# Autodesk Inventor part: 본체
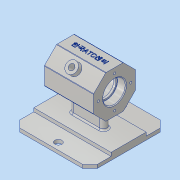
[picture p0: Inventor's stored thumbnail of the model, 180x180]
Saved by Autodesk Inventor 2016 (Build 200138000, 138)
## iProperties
Created: 2018-06
Part Number: 본체
Material: 알루미늄 6061
Document SubType Name: Modeling
Designer: 605-17
Density: 2.7 g/cm^3
Appearance: 알루미늄 - 평지
Mass: 552.439 g
Surface Area: 602.386 cm^2
Volume: 204.607 cm^3
Author: 605-17
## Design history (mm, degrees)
sketch "스케치1"
  geometry: L1 (-45, 55)-(45, 55); L2 (55, 45)-(55, -45); L3 (45, -55)-(-45, -55); L4 (-55, -45)-(-55, 45); L5 (-45, 55)-(-55, 45); L6 (45, 55)-(55, 45); L7 (-45, -55)-(-55, -45); L8 (45, -55)-(55, -45); 7 further points
  constraints: 16 end point, 8 point on line, 2 midpoint, 2 parallel, 2 perpendicular, 1 horizontal, 1 horizontal alignment, 1 vertical alignment
  dimensions: "d0" = 110 distance of point (-55, 55) point (55, 55); "d1" = 10 distance of L1.start point (-55, 55); "d2" = 10 distance of L4.end point (-55, 55) (= d1); "d3" = 10 distance of L1.end point (55, 55) (= d1); "d4" = 10 distance of L2.start point (55, 55) (= d3); "d5" = 10 distance of L3.end point (-55, -55) (= d1); "d6" = 10 distance of L4.start point (-55, -55) (= d5); "d7" = 10 distance of L3.start point (55, -55) (= d1); "d8" = 10 distance of L2.end point (55, -55) (= d7)
extrude "돌출1" new body sketch "스케치1" distance "d9" = 5; taper "d10" = 0 deg
sketch "스케치2"
  geometry: L1 (-55, 45)-(-55, -45) reference; L2 (-45, -55)-(45, -55) reference; L3 (55, -45)-(55, 45) reference; L4 (45, 55)-(-45, 55) reference; L5 (-55, 45)-(-55, -45) reference; L6 (55, -45)-(55, 45) reference; L7 (-55, 25)-(55, 25); L8 (-55, -25)-(55, -25); L9 (55, -25)-(55, 25); L10 (-55, 25)-(-55, -25); 1 further point
  constraints: 8 end point, 4 point on line, 2 collinear, 2 perpendicular
  dimensions: "d11" = 30 distance between parallel lines of L7 L4; "d12" = 30 distance between parallel lines of L2 L8
extrude "돌출2" join sketch "스케치2" distance "d13" = 5; taper "d14" = 0 deg
sketch "스케치3" dims "d15" = 60
  geometry: L1 (25, 10)-(-25, 10) reference; L2 (-30, 74.426)-(-12.426, 92); L3 (-12.426, 92)-(12.426, 92); L4 (12.426, 92)-(30, 74.426); L5 (30, 74.426)-(30, 49.574); L6 (30, 49.574)-(12.426, 32); L7 (12.426, 32)-(-12.426, 32); L8 (-12.426, 32)-(-30, 49.574); L9 (-30, 49.574)-(-30, 74.426); 4 further points
  constraints: 16 end point, 1 coincident, 1 horizontal alignment, 1 midpoint, 1 vertical alignment, 19 other
  dimensions: "d16" = 62 distance of point (0, 0) point (0, 62); "d17" = 92 distance from line of point (0, 0) L3
extrude "돌출3" join sketch "스케치3" stored distance "d18" = 70; taper "d19" = 0 deg
sketch "스케치4"
  geometry: L1 (-19, 5)-(19, 5); L2 (19, -5)-(-19, -5); A1 r 5 centre (19, 0) between (19, -5) and (19, 5); A2 r 5 centre (-19, 0) between (-19, 5) and (-19, -5); 2 further points
  constraints: 4 end point, 4 point on circle, 4 tangent, 2 centre point, 2 horizontal, 1 horizontal alignment, 1 midpoint, 1 vertical alignment
  dimensions: "d20" = 5 radius of A2; "d21" = 38 distance of A1.centre A2.centre
extrude "돌출4" join sketch "스케치4" distance "d22" = 50; taper "d23" = 0 deg
sketch "스케치5"
  geometry: L1 (35, 92)-(35, 74.426) reference; L2 (35, 74.426)-(35, 49.574) reference; L3 (35, 49.574)-(35, 32) reference; L4 (-35, 74.426)-(-35, 92) reference; L5 (-35, 49.574)-(-35, 74.426) reference; L6 (-35, 32)-(-35, 49.574) reference; L7 (35, 62)-(-35, 62); L8 (35, 78)-(23, 78); L9 (23, 78)-(23, 76); L10 (23, 76)-(20, 76); L11 (20, 76)-(20, 87); L12 (20, 87)-(-20, 87); L13 (-20, 87)-(-20, 76); L14 (-20, 76)-(-23, 76); L15 (-23, 76)-(-23, 78); L16 (-23, 78)-(-35, 78); L17 (-35, 78)-(-35, 62); L18 (35, 78)-(35, 62); 1 further point
  constraints: 24 end point, 6 perpendicular, 5 collinear, 5 point on line, 2 midpoint, 1 vertical
  dimensions: "d24" = 32 diameter of L8 L7; "d25" = 28 diameter of L10 L7; "d26" = 50 diameter of L12 L7; "d27" = 12 distance between parallel lines of L1 L9; "d28" = 40 distance between parallel lines of L13 L11
revolve "회전1" sketch "스케치5" stored, may be unused: angle "d29" = 90 deg
sketch "스케치6"
  geometry: C1 r 16 at (-62, 0) reference; 2 further points
  constraints: 1 horizontal alignment
  dimensions: "d30" = 23 distance of C1.centre point (-85, 0)
hole "구멍1" sketch "스케치6" at (-85, 0) diameter "d31" = 3.242; stored, may be unused: countersink angle "d35" = 90 deg, drill point angle "d37" = 118 deg; dims "d32" = 8, "d33" = 4, "d34" = 2, "d36" = 10
sketch "스케치7"
  geometry: L1 (45, 55)-(-45, 55) reference; L2 (-45, -55)-(45, -55) reference; C1 r 5 at (0, 45); C2 r 5 at (0, -45); 1 further point
  constraints: 2 centre point, 2 vertical alignment, 1 equal radius
  dimensions: "d41" = 10 distance from line of L2 C2.centre; "d42" = 10 distance from line of L1 C1.centre; "d43" = 10 diameter of C1
extrude "돌출5" cut sketch "스케치7" distance "d44" = 50; taper "d45" = 0 deg
sketch "스케치8"
  geometry: L1 (0, 0)-(0, 24.853) reference; C1 r 8 at (35, 12.426); 2 further points
  constraints: 1 centre point, 1 horizontal alignment, 1 midpoint, 1 vertical alignment
  dimensions: "d46" = 16 diameter of C1
extrude "돌출6" join sketch "스케치8" distance "d47" = 7; taper "d48" = 0 deg
sketch "스케치9"
  geometry: L1 (70, 42.426)-(0, 42.426) reference; L2 (0, 24.853)-(0, 42.426) reference; 2 further points
  constraints: 1 other
  dimensions: "d49" = 30 distance from line of point (35, 12.426) L1; "d50" = 35 distance from line of point (35, 12.426) L2
feature "엠보싱1" sketch "스케치9" dims "d0" = 110, "d1" = 10, "d2" = 10 (= d1), "d3" = 10 (= d1), "d4" = 10 (= d3), "d5" = 10 (= d1), "d6" = 10 (= d5), "d7" = 10 (= d1), "d8" = 10 (= d7), "d51" = 0.5, "d52" = 0
hole "구멍2" diameter "d55" = 8; stored, may be unused: countersink angle "d59" = 90 deg, drill point angle "d61" = 0 deg; dims "d56" = 8, "d57" = 4, "d58" = 2, "d60" = 20, "d71" = 10, "d72" = 10
chamfer "모따기1" distance "d62" = 1; stored, may be unused: second distance "d63" = 2, angle "d64" = 45 deg
fillet "모깎기1" dims "d65" = 1
fillet "모깎기2" dims "d66" = 0.3
fillet "모깎기3" dims "d67" = 2
fillet "모깎기4" dims "d68" = 3
node "솔리드1"
pattern_circular "원형 패턴1" dims angle "d39" = 360 deg
mirror "대칭1"
